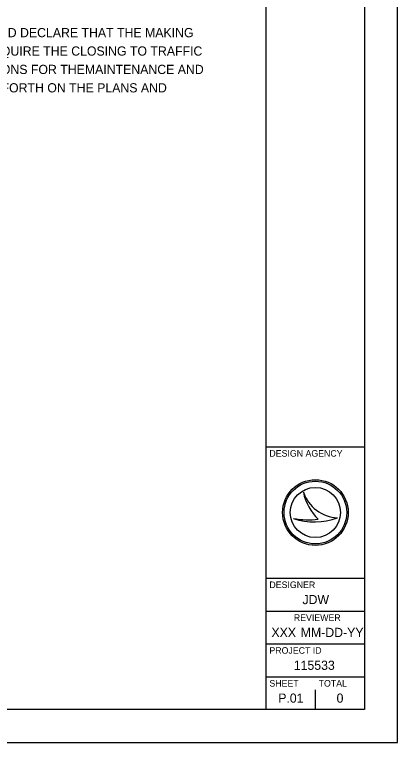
# Model space of a CAD drawing. Extents: x 0 to 34, y 0 to 22.
# Drawn here: x 28.17 to 34, y 0 to 11.08 of the extents above; entities that cross this region are included whole.
import ezdxf

# ---------------------------------------------------------------- set-up
doc = ezdxf.new("R2010")
doc.units = 0
for name, color, linetype in [('SH_Border', 7, 'Continuous'), ('SH_Cut_Line', 7, 'Continuous'), ('SH_Data', 7, 'Continuous')]:
    doc.layers.add(name, color=color, linetype=linetype)

msp = doc.modelspace()

# ---------------------------------------------------------------- linework, layer by layer
at = {"layer": 'SH_Border'}
for p, q in [((32, 0.5), (32, 21.5)), ((32, 4.5), (33.5, 4.5)), ((32, 2.5), (33.5, 2.5)), ((32, 2), (33.5, 2)), ((32, 1.5), (33.5, 1.5)), ((32, 1), (33.5, 1))]:
    msp.add_line(p, q, dxfattribs=at)
msp.add_lwpolyline([(1.5, 21.5), (33.5, 21.5), (33.5, 0.5), (1.5, 0.5)], close=True, dxfattribs=at)
at = {"layer": 'SH_Cut_Line'}
msp.add_lwpolyline([(0, 0), (34, 0), (34, 22), (0, 22)], close=True, dxfattribs=at)
at = {"layer": 'SH_Data'}
for p, q in [((32.567, 3.81), (32.567, 3.81)), ((32.75, 3.5), (32.75, 3.5)), ((32.417, 3.41), (32.417, 3.41)), ((33.087, 3.419), (33.087, 3.419)), ((32.75, 0.5), (32.75, 0.8)), ((32.375, 0.675), (32.375, 0.675))]:
    msp.add_line(p, q, dxfattribs=at)
for radius in [0.5, 0.477, 0.477, 0.382]:
    msp.add_circle((32.75, 3.5), radius, dxfattribs=at)
for centre, radius, start, end in [((33.116, 3.998), 0.58, 198.9257, 198.9319), ((33.347, 3.97), 0.796, 191.6379, 191.6421), ((33.116, 3.998), 0.58, 198.9319, 267.1657), ((33.347, 3.97), 0.796, 191.6421, 226.0947), ((32.739, 4.37), 1.013, 251.4576, 290.0832), ((32.648, 4.654), 1.266, 259.4964, 259.4995), ((32.739, 4.37), 1.013, 251.4527, 251.4576), ((32.648, 4.654), 1.266, 259.4995, 276.6672)]:
    msp.add_arc(centre, radius, start, end, dxfattribs=at)

# ---------------------------------------------------------------- texts
for s, height, p in [(' I HEREBY APPROVE THESE PLANS AND DECLARE THAT THE MAKING ', 0.14, (24.528, 10.735)), ('OF THIS IMPROVEMENT WILL NOT REQUIRE THE CLOSING TO TRAFFIC ', 0.14, (24.528, 10.455)), ('OF THE HIGHWAY AND THAT PROVISIONS FOR THEMAINTENANCE AND ', 0.14, (24.528, 10.175)), ('SAFETY OF TRAFFIC WILL BE AS SET FORTH ON THE PLANS AND ', 0.14, (24.528, 9.895)), ('DESIGN AGENCY', 0.1, (32.05, 4.35)), ('DESIGNER', 0.1, (32.05, 2.35)), ('JDW', 0.14, (32.553, 2.105)), ('REVIEWER', 0.1, (32.422, 1.85)), ('XXX', 0.14, (32.081, 1.605)), ('MM-DD-YY', 0.14, (32.527, 1.605)), ('PROJECT ID', 0.1, (32.05, 1.35)), ('115533', 0.14, (32.421, 1.105)), ('SHEET', 0.1, (32.05, 0.85)), ('TOTAL', 0.1, (32.8, 0.85)), ('P.01', 0.14, (32.184, 0.605)), ('0', 0.14, (33.073, 0.605))]:
    msp.add_text(s, height=height, dxfattribs=at).set_placement(p)

doc.saveas('drawing.dxf')
